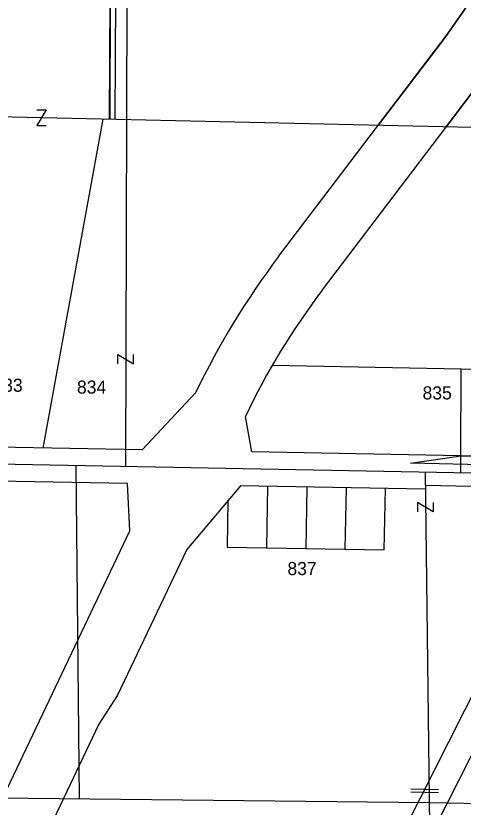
# Model space of a CAD drawing. Extents: x 582596 to 627039, y 145946 to 197316.
# Drawn here: x 616103 to 617809, y 163403 to 166425 of the extents above; entities that cross this region are included whole.
import ezdxf

# ---------------------------------------------------------------- set-up
doc = ezdxf.new("R2010")
doc.units = 0
for name, color, linetype in [('Defpoints 2', 7, 'Continuous'), ('E_RW_EasementUtility', 7, 'Continuous'), ('E_RW_Existing', 7, 'Continuous'), ('E_RW_SixteenthLine', 7, 'Continuous'), ('P_RW_MinorLotLine', 7, 'Continuous'), ('P_RW_PropertyConnector', 7, 'Continuous'), ('P_RW_PropertyLine', 7, 'Continuous'), ('P_RW_QuarterLine', 7, 'Continuous'), ('P_RW_SectionLine', 7, 'Continuous')]:
    doc.layers.add(name, color=color, linetype=linetype)

msp = doc.modelspace()

# ---------------------------------------------------------------- linework, layer by layer
at = {"layer": 'E_RW_EasementUtility'}
for p, q in [((616466.8, 167357.3), (616461.3, 166031.4)), ((616486.8, 167357.2), (616481.3, 166031.3)), ((617608.8, 164716.7), (617801, 164745.1)), ((618115, 164704.5), (617608.8, 164716.7)), ((617609.4, 163461.5), (617715.4, 163459.5)), ((617715.6, 163469.5), (617609.6, 163471.5))]:
    msp.add_line(p, q, dxfattribs=at)
at = {"layer": 'E_RW_Existing'}
for p, q in [((617801.1, 164745.2), (617842.5, 164744.4)), ((617664.8, 164632.7), (617839.7, 164629.4)), ((617807.5, 163757.1), (617548.9, 163247.2))]:
    msp.add_line(p, q, dxfattribs=at)
msp.add_arc((613762.4, 165804.5), 4533.8, 333.1534, 341.9052, dxfattribs=at)
at = {"layer": 'E_RW_SixteenthLine'}
for p, q in [((616529.9, 167355.5), (616521.1, 164703.9)), ((615206.7, 166058.7), (617844.3, 166000.7)), ((616331.4, 164707.4), (616345.2, 163435.4)), ((615010.7, 163449.6), (617679.6, 163421.2)), ((617679.6, 163421.2), (620328.3, 163368.3))]:
    msp.add_line(p, q, dxfattribs=at)
at = {"layer": 'P_RW_MinorLotLine'}
for p, q in [((617801.1, 164745.2), (617801.9, 165077.4)), ((617063.1, 164628.8), (617058.8, 164393.9)), ((617213.1, 164626), (617208.7, 164391.1)), ((617363.1, 164623.2), (617358.7, 164388.3))]:
    msp.add_line(p, q, dxfattribs=at)
msp.add_lwpolyline([(616912.1, 164573.9), (616908.8, 164396.7), (617508.7, 164385.5), (617513, 164620.5)], dxfattribs=at)
at = {"layer": 'P_RW_PropertyConnector'}
for p, q in [((616183.5, 166066.8), (616219.1, 166066.8)), ((616219.1, 166066.8), (616183.5, 166006.9)), ((616201.3, 166036.8), (616201.3, 166036.8)), ((616183.5, 166006.9), (616219.1, 166006.8)), ((616492.4, 165096.7), (616492.4, 165132.3)), ((616492.4, 165132.3), (616552.4, 165096.7)), ((616552.4, 165096.7), (616552.4, 165132.3)), ((616522.4, 165114.5), (616522.4, 165114.5)), ((617635.2, 164566.6), (617635.2, 164530.9)), ((617695.2, 164530.9), (617635.2, 164566.6)), ((617665.2, 164548.8), (617665.2, 164548.8)), ((617695.2, 164566.6), (617695.2, 164530.9))]:
    msp.add_line(p, q, dxfattribs=at)
at = {"layer": 'P_RW_PropertyLine'}
for p, q in [((616466.5, 167357.1), (616459.7, 166031.2)), ((617844.5, 166494.3), (617778.2, 166395.7)), ((617778.2, 166395.7), (617844.5, 166494.3)), ((617778.2, 166395.7), (617750.9, 166357.7)), ((617750.9, 166357.7), (617778.2, 166395.7)), ((617750.9, 166357.7), (617722.9, 166320.1)), ((617722.9, 166320.1), (617750.9, 166357.7)), ((617105.4, 165505.6), (617724, 166321.6)), ((617722.9, 166320.1), (617485.6, 166007.1)), ((617485.6, 166007.1), (617722.9, 166320.1)), ((617272.7, 165378.7), (617843.6, 166131.8)), ((617744.7, 166001.5), (617843.6, 166131.9)), ((617843.6, 166131.9), (617744.7, 166001.5)), ((616434.4, 166030.2), (616206.4, 164774.8)), ((617485.6, 166007.1), (617484.6, 166007.2)), ((617484.6, 166007.2), (617485.6, 166007.1)), ((617105.8, 165506.1), (617105.5, 165505.8)), ((617081.5, 165090.7), (617801.9, 165077.4)), ((617801.9, 165077.3), (618228.6, 165064.5)), ((616789, 164985.2), (616584.9, 164767.7)), ((617003.6, 164760), (616978.6, 164895)), ((616584.9, 164767.7), (615962.7, 164779.3)), ((617801.1, 164745.2), (617003.6, 164760)), ((617800.9, 164680.1), (617801.1, 164745.2)), ((616528.5, 164638.8), (615625.8, 164655.5)), ((616528.5, 164638.8), (615626.1, 164655.5)), ((616538.6, 164459), (616528.5, 164638.8)), ((616959.7, 164630.8), (616755.2, 164387.5)), ((616959.7, 164630.7), (616755.3, 164387.3)), ((617665, 164617.7), (616959.7, 164630.8)), ((617665, 164617.7), (616959.7, 164630.7)), ((615922.5, 163164.4), (616538.6, 164459)), ((616755.2, 164387.5), (616490.6, 163831.4)), ((616755.3, 164387.3), (616490.7, 163831.3)), ((616490.6, 163831.4), (616419.4, 163720)), ((616490.7, 163831.3), (616419.6, 163719.8)), ((616419.4, 163720), (616123.7, 163098.5)), ((616419.6, 163719.8), (616123.9, 163098.3)), ((617586.5, 163099), (617896.8, 163711.9))]:
    msp.add_line(p, q, dxfattribs=at)
for radius in [2982.9, 2772.9]:
    msp.add_arc((619482.5, 163703.6), radius, 142.8351, 154.5529, dxfattribs=at)
at = {"layer": 'P_RW_QuarterLine'}
msp.add_line((617664.2, 164682.7), (617695.9, 162084), dxfattribs=at)
at = {"layer": 'P_RW_SectionLine'}
msp.add_line((617840.9, 164679.4), (615201.2, 164728.4), dxfattribs=at)

# ---------------------------------------------------------------- texts
at = {"layer": 'Defpoints 2'}
for s, p in [('833', (616017.7, 164989.6)), ('834', (616336.3, 164982.6)), ('835', (617654.5, 164960.4)), ('837', (617139.1, 164289.6))]:
    msp.add_text(s, height=50, dxfattribs=at).set_placement(p)

doc.saveas('drawing.dxf')
